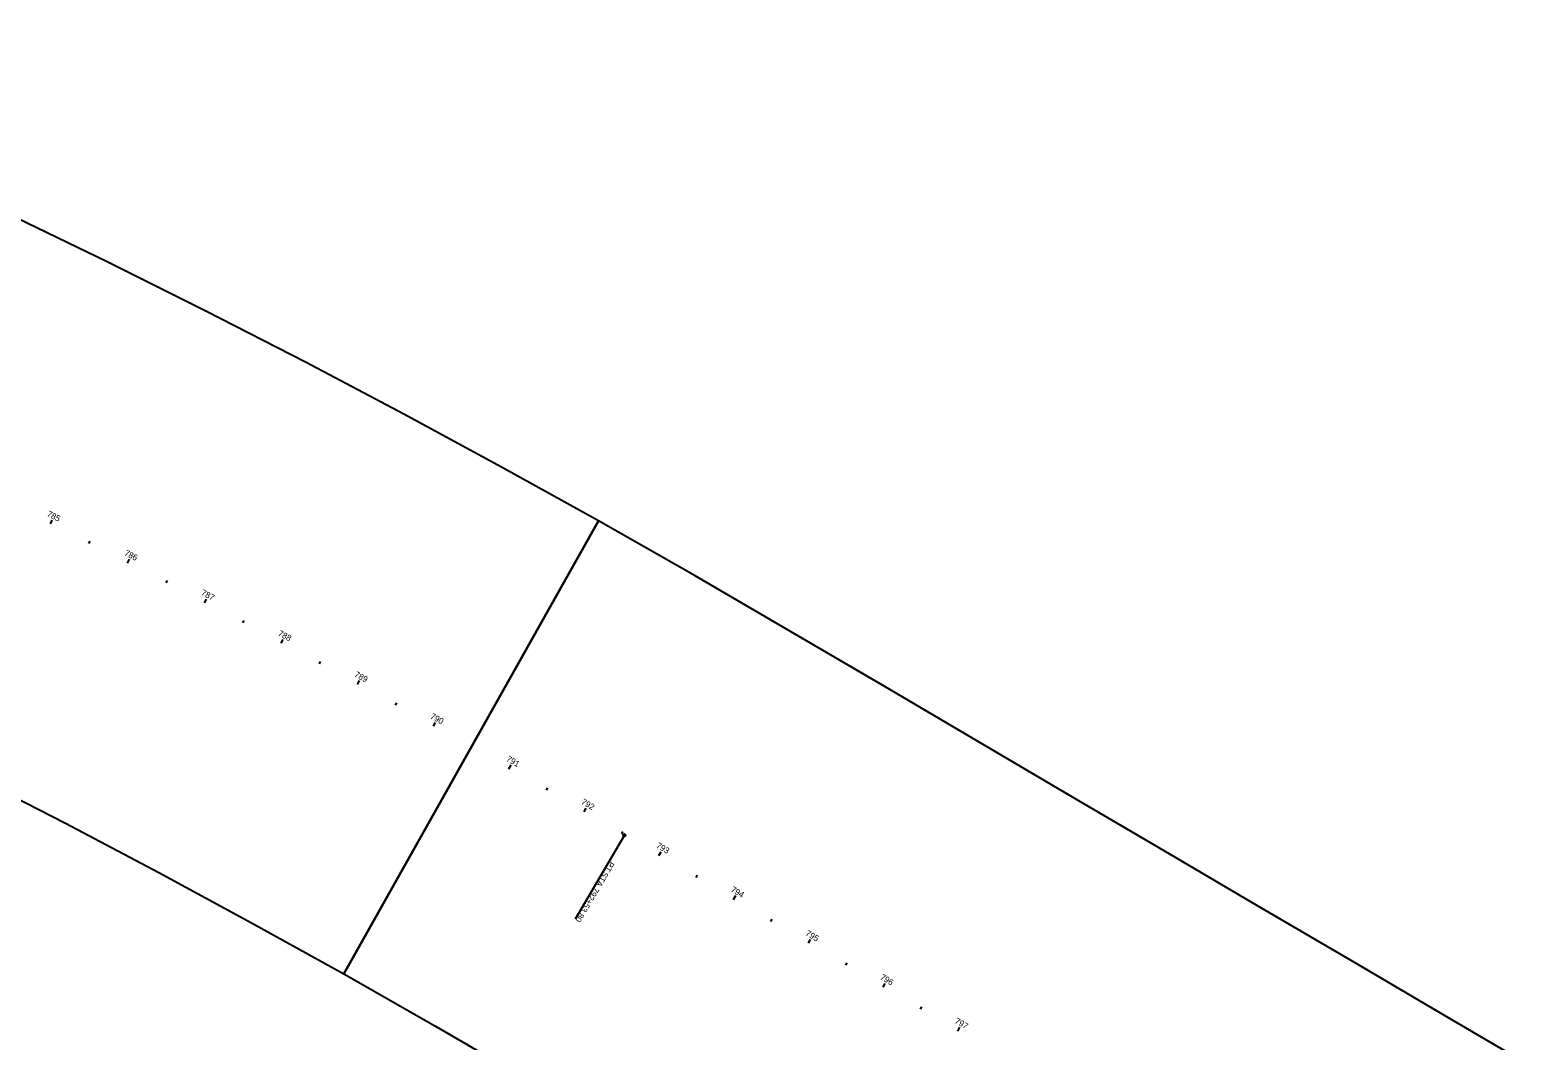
# Model space of a CAD drawing. Extents: x 75725 to 90554, y 518585 to 527848.
# Drawn here: x 81233 to 82972, y 525680 to 526847 of the extents above; entities that cross this region are included whole.
import ezdxf

# ---------------------------------------------------------------- set-up
doc = ezdxf.new("R2010")
doc.units = 0
for name, color, linetype in [('GE_P_Alignment_100_Cardinal_Points', 7, 'Continuous'), ('GE_P_Alignment_100_Stations', 7, 'Continuous'), ('SH_Named_Boundary', 7, 'Continuous')]:
    doc.layers.add(name, color=color, linetype=linetype)

msp = doc.modelspace()

# ---------------------------------------------------------------- linework, layer by layer
at = {"layer": 'GE_P_Alignment_100_Cardinal_Points'}
msp.add_line((81918.3, 525917), (81861.3, 525820), dxfattribs=at)
msp.add_circle((81918.3, 525917), 1.5, dxfattribs=at)
at = {"layer": 'GE_P_Alignment_100_Stations'}
for p, q in [((81255.9, 526276.5), (81258.1, 526281)), ((81300.5, 526254), (81301.9, 526256.7)), ((81345.1, 526231.3), (81347.4, 526235.8)), ((81389.5, 526208.4), (81390.9, 526211.1)), ((81433.9, 526185.4), (81436.2, 526189.8)), ((81478.2, 526162.1), (81479.6, 526164.8)), ((81522.3, 526138.7), (81524.7, 526143.1)), ((81566.4, 526115), (81567.8, 526117.6)), ((81610.3, 526091.2), (81612.7, 526095.6)), ((81654.2, 526067.1), (81655.6, 526069.8)), ((81697.9, 526042.9), (81700.3, 526047.3)), ((81741.5, 526018.5), (81743, 526021.1)), ((81785.1, 525993.9), (81787.5, 525998.2)), ((81828.5, 525969.1), (81830, 525971.7)), ((81871.8, 525944.1), (81874.3, 525948.4)), ((81915, 525918.9), (81916.5, 525921.5)), ((81958.1, 525893.6), (81960.6, 525897.9)), ((82001.2, 525868.3), (82002.7, 525870.9)), ((82044.3, 525843), (82046.9, 525847.3)), ((82087.4, 525817.6), (82089, 525820.2)), ((82130.6, 525792.3), (82133.1, 525796.6)), ((82173.7, 525767), (82175.2, 525769.6)), ((82216.8, 525741.7), (82219.3, 525746)), ((82259.9, 525716.3), (82261.4, 525718.9)), ((82303, 525691), (82305.5, 525695.3))]:
    msp.add_line(p, q, dxfattribs=at)
at = {"layer": 'SH_Named_Boundary'}
for points in [[(80738.5, 526846.6), (80503.1, 526294.7), (80614.8, 526246.3), (80726, 526196.7), (80836.6, 526145.9), (80946.6, 526093.9), (81056.1, 526040.7), (81165, 525986.3), (81273.3, 525930.8), (81381, 525874), (81488.1, 525816.1), (81594.5, 525757), (81888.6, 526280), (81776.5, 526342.2), (81663.7, 526403.3), (81550.2, 526463.1), (81436.1, 526521.6), (81321.3, 526579), (81205.9, 526635), (81089.9, 526689.8), (80973.4, 526743.4), (80856.2, 526795.6)], [(81888.6, 526280), (81594.5, 525757), (81700.3, 525696.8), (81806.2, 525634.9), (81914, 525571.6), (82021.7, 525508.3), (82129.5, 525445), (82237.3, 525381.7), (82345.1, 525318.4), (82452.9, 525255.1), (82560.6, 525191.7), (82668.4, 525128.4), (82972.3, 525645.8), (82864.5, 525709.1), (82756.8, 525772.4), (82649, 525835.7), (82541.2, 525899), (82433.4, 525962.3), (82325.6, 526025.7), (82217.9, 526089), (82110.1, 526152.3), (82000.1, 526216.5)]]:
    msp.add_lwpolyline(points, close=True, dxfattribs=at)

# ---------------------------------------------------------------- texts
at = {"layer": 'GE_P_Alignment_100_Cardinal_Points'}
for s, p in [('PT', (81901.2, 525887.7)), (' STA. ', (81895.6, 525878.2)), ('792+53.80', (81883.6, 525857.8))]:
    msp.add_text(s, height=7, rotation=239.5684, dxfattribs=at).set_placement(p)
at = {"layer": 'GE_P_Alignment_100_Stations'}
for s, rotation, p in [('785', 333.3972, (81251.3, 526285.8)), ('786', 332.8972, (81340.5, 526240.7)), ('787', 332.3972, (81429.2, 526194.9)), ('788', 331.8972, (81517.9, 526148.1)), ('789', 331.3972, (81606, 526100.6)), ('790', 330.8972, (81693.6, 526052.4)), ('791', 330.3972, (81781.3, 526003.2)), ('792', 329.8972, (81867.8, 525953.6)), ('793', 329.5684, (81954.2, 525903.2)), ('794', 329.5684, (82040.4, 525852.5)), ('795', 329.5684, (82126.6, 525801.9)), ('796', 329.5684, (82212.7, 525751.3)), ('797', 329.5684, (82298.8, 525700.7))]:
    msp.add_text(s, height=7, rotation=rotation, dxfattribs=at).set_placement(p)

doc.saveas('drawing.dxf')
